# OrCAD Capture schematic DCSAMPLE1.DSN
size A
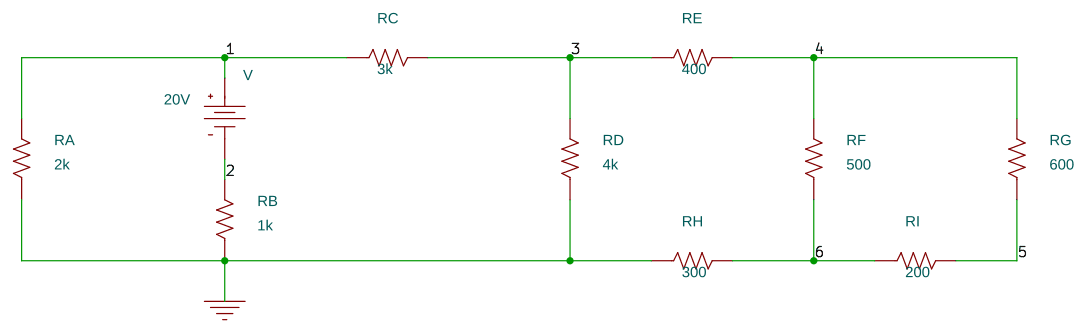
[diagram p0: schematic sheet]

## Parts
RA  2k  [AX/RC05]
RB  1k  [AX/RC05]
RC  3k  [AX/RC05]
RD  4k  [AX/RC05]
RE  400  [AX/RC05]
RF  500  [AX/RC05]
RG  600  [AX/RC05]
RH  300  [AX/RC05]
RI  200  [AX/RC05]
V  VDC

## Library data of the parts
RA RB RC RD RE RF RG RH RI = R
V = VDC: DC: 20V

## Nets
0: RA.1 RB.1 RD.1 RH.1
1: RA.2 RC.1 V.0(+)
2: RB.2 V.1(-)
3: RC.2 RD.2 RE.1
4: RE.2 RF.2 RG.2
5: RG.1 RI.2
6: RF.1 RH.2 RI.1
